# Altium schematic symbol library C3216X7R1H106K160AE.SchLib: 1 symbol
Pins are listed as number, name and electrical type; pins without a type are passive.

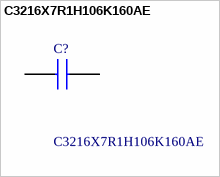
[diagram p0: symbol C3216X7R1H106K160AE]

## C3216X7R1H106K160AE
designator C?
MULTILAYER CERAMIC CHIP CAPACITORS, 3216, Commercial grade, general (Up to 75V); Manufacturer_Name: TDK; Geometry.Height: 1.8mm
footprint CAPC3216X180N
pins: 1, 2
